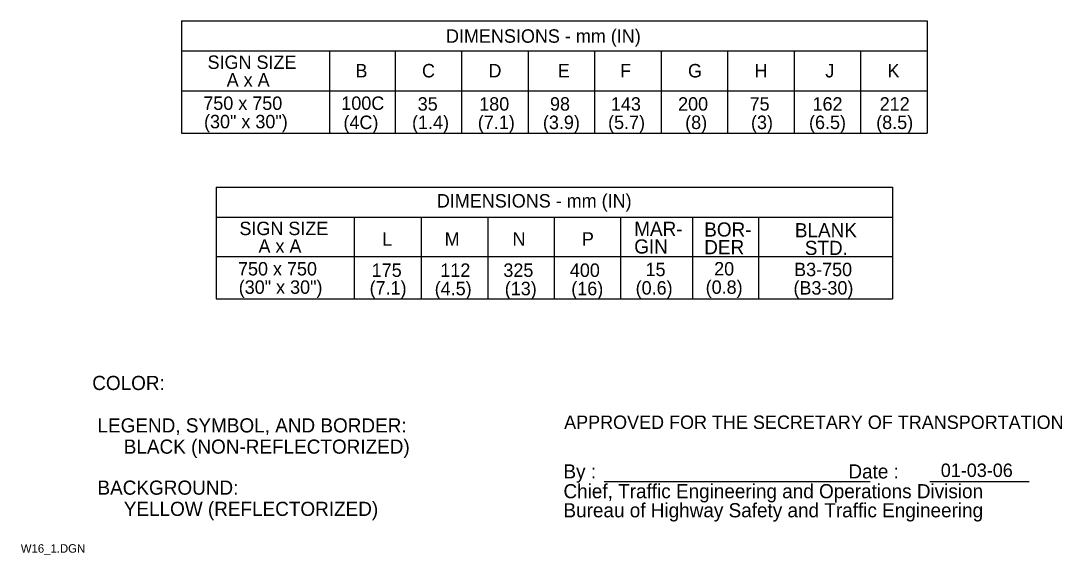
# Model space of a CAD drawing. Extents: x 0.012 to 0.196, y 0.004 to 0.259.
# Drawn here: x 0.0124 to 0.1964, y 0.0039 to 0.0984 of the extents above; entities that cross this region are included whole.
import ezdxf

# ---------------------------------------------------------------- set-up
doc = ezdxf.new("R2010")
doc.units = 0
for name, color, linetype in [('1', 7, 'Continuous'), ('3', 7, 'Continuous'), ('4', 7, 'Continuous')]:
    doc.layers.add(name, color=color, linetype=linetype)

msp = doc.modelspace()

# ---------------------------------------------------------------- linework, layer by layer
at = {"layer": '1'}
for p, q in [((0.11544, 0.01695), (0.16242, 0.01695)), ((0.17295, 0.01695), (0.1905, 0.01695))]:
    msp.add_line(p, q, dxfattribs=at)
at = {"layer": '3'}
for p, q in [((0.04075, 0.09838), (0.1725, 0.09838)), ((0.04075, 0.09838), (0.04075, 0.0785)), ((0.1725, 0.09838), (0.1725, 0.0785)), ((0.1725, 0.093), (0.04075, 0.093)), ((0.06689, 0.09305), (0.06689, 0.07855)), ((0.0785, 0.093), (0.0785, 0.0785)), ((0.09025, 0.093), (0.09025, 0.0785)), ((0.102, 0.093), (0.102, 0.0785)), ((0.11375, 0.093), (0.11375, 0.0785)), ((0.1255, 0.093), (0.1255, 0.0785)), ((0.13725, 0.093), (0.13725, 0.0785)), ((0.149, 0.093), (0.149, 0.0785)), ((0.16075, 0.093), (0.16075, 0.0785)), ((0.04075, 0.086), (0.1725, 0.086)), ((0.04075, 0.0785), (0.1725, 0.0785)), ((0.04688, 0.069), (0.16637, 0.069)), ((0.04688, 0.069), (0.04688, 0.04925)), ((0.16637, 0.069), (0.16637, 0.04925)), ((0.16637, 0.06363), (0.04688, 0.06363)), ((0.0713, 0.06362), (0.0713, 0.04925)), ((0.08313, 0.06363), (0.08313, 0.04925)), ((0.09488, 0.06363), (0.09488, 0.04925)), ((0.10662, 0.06363), (0.10662, 0.04925)), ((0.1183, 0.06362), (0.1183, 0.04925)), ((0.13106, 0.06362), (0.13106, 0.04925)), ((0.14271, 0.06362), (0.14271, 0.04925)), ((0.04688, 0.05675), (0.16637, 0.05675)), ((0.04688, 0.04925), (0.16637, 0.04925))]:
    msp.add_line(p, q, dxfattribs=at)

# ---------------------------------------------------------------- texts
at = {"layer": '1'}
for s, height, p in [('COLOR:', 0.0025, (0.025, 0.03313)), (' LEGEND, SYMBOL, AND BORDER:', 0.0024998, (0.025, 0.02563)), ('APPROVED FOR THE SECRETARY OF TRANSPORTATION', 0.0023752, (0.10837, 0.02625)), ('      BLACK (NON-REFLECTORIZED)', 0.0024998, (0.025, 0.02188)), ('By :                                                Date :', 0.0024998, (0.10825, 0.0175)), (' BACKGROUND:', 0.0024998, (0.025, 0.01463)), ('Chief, Traffic Engineering and Operations Division', 0.0024998, (0.10825, 0.014)), ('      YELLOW (REFLECTORIZED)', 0.0024998, (0.025, 0.01088)), ('Bureau of Highway Safety and Traffic Engineering', 0.0024998, (0.10825, 0.01063)), ('W16_1.DGN', 0.0015, (0.01238, 0.00438))]:
    msp.add_text(s, height=height, dxfattribs=at).set_placement(p)
at = {"layer": '3'}
for s, height, p in [('DIMENSIONS - mm (IN)', 0.0023752, (0.0875, 0.0945)), ('SIGN SIZE', 0.002375, (0.04537, 0.08987)), ('B', 0.00238, (0.0715, 0.08837)), ('C', 0.00238, (0.08325, 0.08837)), ('D', 0.00238, (0.095, 0.08837)), ('E', 0.00238, (0.10725, 0.08837)), ('F', 0.00238, (0.11825, 0.08837)), ('G', 0.00238, (0.13025, 0.08837)), ('H', 0.00238, (0.142, 0.08837)), ('J', 0.00238, (0.1545, 0.08837)), ('K', 0.00238, (0.1655, 0.08837)), ('A x A', 0.002375, (0.04875, 0.08675)), ('750 x 750', 0.002375, (0.04462, 0.08263)), ('100C', 0.002375, (0.069, 0.08263)), ('35', 0.002375, (0.0825, 0.0825)), ('180', 0.002375, (0.09337, 0.0825)), ('98', 0.002375, (0.10587, 0.0825)), ('143', 0.002375, (0.11663, 0.0825)), ('200', 0.002375, (0.1285, 0.0825)), ('75', 0.002375, (0.14113, 0.0825)), ('162', 0.002375, (0.15225, 0.0825)), ('212', 0.002375, (0.16412, 0.0825)), ('(30" x 30")', 0.0023752, (0.04475, 0.07938)), ('(4C)', 0.002375, (0.06938, 0.07925)), ('(1.4)', 0.002375, (0.0815, 0.07925)), ('(7.1)', 0.002375, (0.09312, 0.07925)), ('(3.9)', 0.002375, (0.10462, 0.07925)), ('(5.7)', 0.002375, (0.11613, 0.07925)), ('(8)', 0.002375, (0.12975, 0.07925)), ('(3)', 0.002375, (0.14138, 0.07925)), ('(6.5)', 0.002375, (0.15163, 0.07925)), ('(8.5)', 0.002375, (0.1635, 0.07925)), ('DIMENSIONS - mm (IN)', 0.0023752, (0.08588, 0.06538)), ('SIGN SIZE', 0.002375, (0.051, 0.0605)), ('MAR-', 0.0025, (0.12075, 0.06037)), ('BOR-', 0.0025, (0.13312, 0.06025)), ('BLANK', 0.0025, (0.14913, 0.06012)), ('L', 0.00238, (0.07625, 0.05863)), ('M', 0.00238, (0.08725, 0.05863)), ('N', 0.00238, (0.09925, 0.05863)), ('P', 0.00238, (0.1115, 0.05863)), ('A x A', 0.002375, (0.05437, 0.05738)), ('GIN', 0.0025, (0.12075, 0.05725)), ('DER', 0.0025, (0.13312, 0.05713)), ('STD.', 0.0025, (0.15088, 0.057)), ('750 x 750', 0.002375, (0.05075, 0.05337)), ('175', 0.002375, (0.07437, 0.05312)), ('112', 0.002375, (0.0865, 0.05312)), ('325', 0.002375, (0.09763, 0.05312)), ('400', 0.002375, (0.10938, 0.05312)), ('15', 0.002375, (0.12275, 0.05325)), ('20', 0.002375, (0.13487, 0.05337)), ('B3-750', 0.002375, (0.149, 0.05325)), ('(30" x 30")', 0.0023752, (0.05088, 0.05013)), ('(7.1)', 0.002375, (0.074, 0.05)), ('(4.5)', 0.002375, (0.0855, 0.04988)), ('(13)', 0.002375, (0.09788, 0.04988)), ('(16)', 0.002375, (0.10963, 0.04988)), ('(0.6)', 0.002375, (0.121, 0.05)), ('(0.8)', 0.002375, (0.13337, 0.05013)), ('(B3-30)', 0.002375, (0.14888, 0.05))]:
    msp.add_text(s, height=height, dxfattribs=at).set_placement(p)
at = {"layer": '4'}
msp.add_text('01-03-06', height=0.002375, dxfattribs=at).set_placement((0.17491, 0.01776))

doc.saveas('drawing.dxf')
